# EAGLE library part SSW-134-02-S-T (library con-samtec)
THROUGH-HOLE .025" SQ POST SOCKET Source: Samtec SSW.pdf
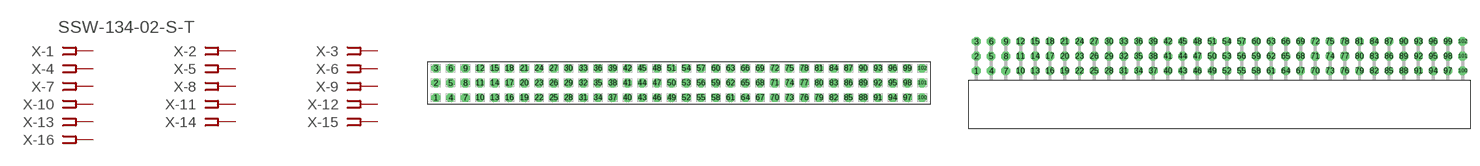
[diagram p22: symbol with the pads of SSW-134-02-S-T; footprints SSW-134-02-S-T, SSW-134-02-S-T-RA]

Designator prefix X; gates -1=FPINV -2=FPIN -3=FPIN -4=FPIN -5=FPIN -6=FPIN -7=FPIN -8=FPIN -9=FPIN -10=FPIN -11=FPIN -12=FPIN -13=FPIN -14=FPIN -15=FPIN -16=FPIN -17=FPIN -18=FPIN -19=FPIN -20=FPIN -21=FPIN -22=FPIN -23=FPIN -24=FPIN -25=FPIN -26=FPIN -27=FPIN -28=FPIN -29=FPIN -30=FPIN -31=FPIN -32=FPIN -33=FPIN -34=FPIN -35=FPIN -36=FPIN -37=FPIN -38=FPIN -39=FPIN -40=FPIN -41=FPIN -42=FPIN -43=FPIN -44=FPIN -45=FPIN -46=FPIN -47=FPIN -48=FPIN -49=FPIN -50=FPIN -51=FPIN -52=FPIN -53=FPIN -54=FPIN -55=FPIN -56=FPIN -57=FPIN -58=FPIN -59=FPIN -60=FPIN -61=FPIN -62=FPIN -63=FPIN -64=FPIN -65=FPIN -66=FPIN -67=FPIN -68=FPIN -69=FPIN -70=FPIN -71=FPIN -72=FPIN -73=FPIN -74=FPIN -75=FPIN -76=FPIN -77=FPIN -78=FPIN -79=FPIN -80=FPIN -81=FPIN -82=FPIN -83=FPIN -84=FPIN -85=FPIN -86=FPIN -87=FPIN -88=FPIN -89=FPIN -90=FPIN -91=FPIN -92=FPIN -93=FPIN -94=FPIN -95=FPIN -96=FPIN -97=FPIN -98=FPIN -99=FPIN -100=FPIN -101=FPIN -102=FPIN

## SSW-134-02-S-T (OC_FARNELL: unknown; OC_NEWARK: unknown)  [SSW-134-02-S-T]
1  -1:1  pas
2  -2:1  pas
3  -3:1  pas
4  -4:1  pas
5  -5:1  pas
6  -6:1  pas
7  -7:1  pas
8  -8:1  pas
9  -9:1  pas
10  -10:1  pas
11  -11:1  pas
12  -12:1  pas
13  -13:1  pas
14  -14:1  pas
15  -15:1  pas
16  -16:1  pas
17  -17:1  pas
18  -18:1  pas
19  -19:1  pas
20  -20:1  pas
21  -21:1  pas
22  -22:1  pas
23  -23:1  pas
24  -24:1  pas
25  -25:1  pas
26  -26:1  pas
27  -27:1  pas
28  -28:1  pas
29  -29:1  pas
30  -30:1  pas
31  -31:1  pas
32  -32:1  pas
33  -33:1  pas
34  -34:1  pas
35  -35:1  pas
36  -36:1  pas
37  -37:1  pas
38  -38:1  pas
39  -39:1  pas
40  -40:1  pas
41  -41:1  pas
42  -42:1  pas
43  -43:1  pas
44  -44:1  pas
45  -45:1  pas
46  -46:1  pas
47  -47:1  pas
48  -48:1  pas
49  -49:1  pas
50  -50:1  pas
51  -51:1  pas
52  -52:1  pas
53  -53:1  pas
54  -54:1  pas
55  -55:1  pas
56  -56:1  pas
57  -57:1  pas
58  -58:1  pas
59  -59:1  pas
60  -60:1  pas
61  -61:1  pas
62  -62:1  pas
63  -63:1  pas
64  -64:1  pas
65  -65:1  pas
66  -66:1  pas
67  -67:1  pas
68  -68:1  pas
69  -69:1  pas
70  -70:1  pas
71  -71:1  pas
72  -72:1  pas
73  -73:1  pas
74  -74:1  pas
75  -75:1  pas
76  -76:1  pas
77  -77:1  pas
78  -78:1  pas
79  -79:1  pas
80  -80:1  pas
81  -81:1  pas
82  -82:1  pas
83  -83:1  pas
84  -84:1  pas
85  -85:1  pas
86  -86:1  pas
87  -87:1  pas
88  -88:1  pas
89  -89:1  pas
90  -90:1  pas
91  -91:1  pas
92  -92:1  pas
93  -93:1  pas
94  -94:1  pas
95  -95:1  pas
96  -96:1  pas
97  -97:1  pas
98  -98:1  pas
99  -99:1  pas
100  -100:1  pas
101  -101:1  pas
102  -102:1  pas

## SSW-134-02-S-TRA (OC_FARNELL: unknown; OC_NEWARK: unknown)  [SSW-134-02-S-T-RA]
Pads as for SSW-134-02-S-T

## Footprint SSW-134-02-S-T (pad centres in mm)
THROUGH-HOLE .025" SQ POST SOCKET Source: Samtec SSW.pdf
drill 1 pad 1.5 octagon: 1 -41.91,-2.54; 2 -41.91,0; 3 -41.91,2.54; 4 -39.37,-2.54; 5 -39.37,0; 6 -39.37,2.54; 7 -36.83,-2.54; 8 -36.83,0; 9 -36.83,2.54; 10 -34.29,-2.54; 11 -34.29,0; 12 -34.29,2.54; 13 -31.75,-2.54; 14 -31.75,0; 15 -31.75,2.54; 16 -29.21,-2.54; 17 -29.21,0; 18 -29.21,2.54; 19 -26.67,-2.54; 20 -26.67,0; 21 -26.67,2.54; 22 -24.13,-2.54; 23 -24.13,0; 24 -24.13,2.54; 25 -21.59,-2.54; 26 -21.59,0; 27 -21.59,2.54; 28 -19.05,-2.54; 29 -19.05,0; 30 -19.05,2.54; 31 -16.51,-2.54; 32 -16.51,0; 33 -16.51,2.54; 34 -13.97,-2.54; 35 -13.97,0; 36 -13.97,2.54; 37 -11.43,-2.54; 38 -11.43,0; 39 -11.43,2.54; 40 -8.89,-2.54; 41 -8.89,0; 42 -8.89,2.54; 43 -6.35,-2.54; 44 -6.35,0; 45 -6.35,2.54; 46 -3.81,-2.54; 47 -3.81,0; 48 -3.81,2.54; 49 -1.27,-2.54; 50 -1.27,0; 51 -1.27,2.54; 52 1.27,-2.54; 53 1.27,0; 54 1.27,2.54; 55 3.81,-2.54; 56 3.81,0; 57 3.81,2.54; 58 6.35,-2.54; 59 6.35,0; 60 6.35,2.54; 61 8.89,-2.54; 62 8.89,0; 63 8.89,2.54; 64 11.43,-2.54; 65 11.43,0; 66 11.43,2.54; 67 13.97,-2.54; 68 13.97,0; 69 13.97,2.54; 70 16.51,-2.54; 71 16.51,0; 72 16.51,2.54; 73 19.05,-2.54; 74 19.05,0; 75 19.05,2.54; 76 21.59,-2.54; 77 21.59,0; 78 21.59,2.54; 79 24.13,-2.54; 80 24.13,0; 81 24.13,2.54; 82 26.67,-2.54; 83 26.67,0; 84 26.67,2.54; 85 29.21,-2.54; 86 29.21,0; 87 29.21,2.54; 88 31.75,-2.54; 89 31.75,0; 90 31.75,2.54; 91 34.29,-2.54; 92 34.29,0; 93 34.29,2.54; 94 36.83,-2.54; 95 36.83,0; 96 36.83,2.54; 97 39.37,-2.54; 98 39.37,0; 99 39.37,2.54; 100 41.91,-2.54; 101 41.91,0; 102 41.91,2.54

## Footprint SSW-134-02-S-T-RA (pad centres in mm)
THROUGH-HOLE .025" SQ POST SOCKET Source: Samtec SSW.pdf
drill 1 pad 1.5 octagon: 1 -41.91,1.524; 2 -41.91,4.064; 3 -41.91,6.604; 4 -39.37,1.524; 5 -39.37,4.064; 6 -39.37,6.604; 7 -36.83,1.524; 8 -36.83,4.064; 9 -36.83,6.604; 10 -34.29,1.524; 11 -34.29,4.064; 12 -34.29,6.604; 13 -31.75,1.524; 14 -31.75,4.064; 15 -31.75,6.604; 16 -29.21,1.524; 17 -29.21,4.064; 18 -29.21,6.604; 19 -26.67,1.524; 20 -26.67,4.064; 21 -26.67,6.604; 22 -24.13,1.524; 23 -24.13,4.064; 24 -24.13,6.604; 25 -21.59,1.524; 26 -21.59,4.064; 27 -21.59,6.604; 28 -19.05,1.524; 29 -19.05,4.064; 30 -19.05,6.604; 31 -16.51,1.524; 32 -16.51,4.064; 33 -16.51,6.604; 34 -13.97,1.524; 35 -13.97,4.064; 36 -13.97,6.604; 37 -11.43,1.524; 38 -11.43,4.064; 39 -11.43,6.604; 40 -8.89,1.524; 41 -8.89,4.064; 42 -8.89,6.604; 43 -6.35,1.524; 44 -6.35,4.064; 45 -6.35,6.604; 46 -3.81,1.524; 47 -3.81,4.064; 48 -3.81,6.604; 49 -1.27,1.524; 50 -1.27,4.064; 51 -1.27,6.604; 52 1.27,1.524; 53 1.27,4.064; 54 1.27,6.604; 55 3.81,1.524; 56 3.81,4.064; 57 3.81,6.604; 58 6.35,1.524; 59 6.35,4.064; 60 6.35,6.604; 61 8.89,1.524; 62 8.89,4.064; 63 8.89,6.604; 64 11.43,1.524; 65 11.43,4.064; 66 11.43,6.604; 67 13.97,1.524; 68 13.97,4.064; 69 13.97,6.604; 70 16.51,1.524; 71 16.51,4.064; 72 16.51,6.604; 73 19.05,1.524; 74 19.05,4.064; 75 19.05,6.604; 76 21.59,1.524; 77 21.59,4.064; 78 21.59,6.604; 79 24.13,1.524; 80 24.13,4.064; 81 24.13,6.604; 82 26.67,1.524; 83 26.67,4.064; 84 26.67,6.604; 85 29.21,1.524; 86 29.21,4.064; 87 29.21,6.604; 88 31.75,1.524; 89 31.75,4.064; 90 31.75,6.604; 91 34.29,1.524; 92 34.29,4.064; 93 34.29,6.604; 94 36.83,1.524; 95 36.83,4.064; 96 36.83,6.604; 97 39.37,1.524; 98 39.37,4.064; 99 39.37,6.604; 100 41.91,1.524; 101 41.91,4.064; 102 41.91,6.604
